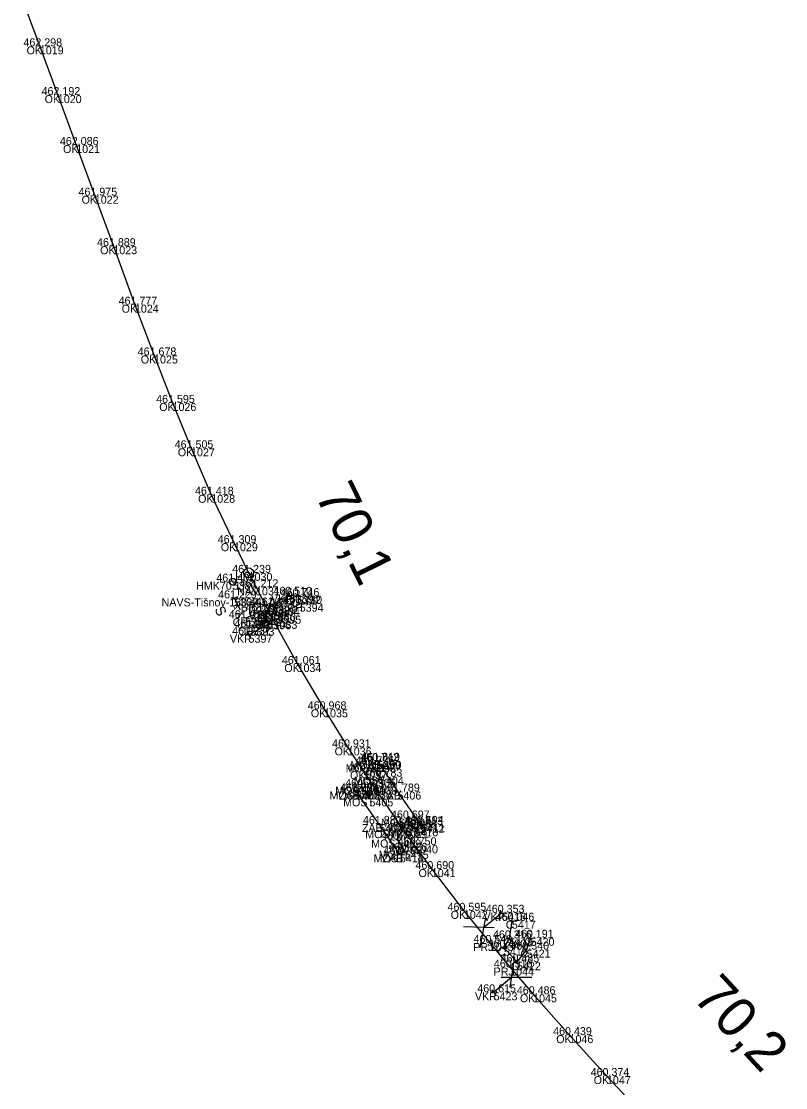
# Model space of a CAD drawing. Extents: x -621782 to -610392, y -1141853 to -1122321.
# Drawn here: x -621297.7 to -621183, y -1126701.5 to -1126541.6 of the extents above; entities that cross this region are included whole.
import ezdxf

# ---------------------------------------------------------------- set-up
doc = ezdxf.new("R2010")
doc.units = 0
for name, color, linetype in [('Vrstva 1', 7, 'Continuous'), ('Vrstva 17', 7, 'Continuous'), ('Vrstva 18', 7, 'Continuous'), ('Vrstva 4', 7, 'Continuous'), ('Vrstva 51', 7, 'Continuous'), ('Vrstva 6', 7, 'Continuous'), ('Vrstva 60', 7, 'Continuous'), ('Vrstva 61', 7, 'Continuous'), ('Vrstva 62', 7, 'Continuous'), ('Vrstva 7', 7, 'Continuous')]:
    doc.layers.add(name, color=color, linetype=linetype)

msp = doc.modelspace()

# ---------------------------------------------------------------- linework, layer by layer
at = {"layer": 'Vrstva 1'}
msp.add_lwpolyline([(-621297.67, -1126537.82), (-621294.89, -1126545.32), (-621292.19, -1126552.63), (-621289.43, -1126560.12), (-621286.64, -1126567.72), (-621283.86, -1126575.29), (-621280.62, -1126584.06), (-621277.75, -1126591.68), (-621274.98, -1126598.8), (-621272.2, -1126605.6), (-621269.16, -1126612.57), (-621265.75, -1126619.83), (-621263.56, -1126624.28), (-621262.45, -1126626.44), (-621260.94, -1126629.35), (-621259.82, -1126631.47), (-621256.22, -1126637.95), (-621252.24, -1126644.74), (-621248.68, -1126650.45), (-621246.36, -1126654.03), (-621244.83, -1126656.34), (-621240.33, -1126662.87), (-621238.72, -1126665.13), (-621236.08, -1126668.7), (-621231.26, -1126674.96), (-621227.37, -1126679.78), (-621224.31, -1126683.46), (-621220.87, -1126687.47), (-621215.41, -1126693.6), (-621209.79, -1126699.74), (-621206.18, -1126703.65)], dxfattribs=at)
at = {"layer": 'Vrstva 17'}
for points in [[(-621244.2, -1126652.45), (-621241.23, -1126657.07), (-621237.76, -1126662.06)], [(-621240.87, -1126666.49), (-621243.96, -1126661.94), (-621247.42, -1126657.07)]]:
    msp.add_lwpolyline(points, dxfattribs=at)
at = {"layer": 'Vrstva 18'}
for points in [[(-621247.48, -1126657.05), (-621246.62, -1126656.41), (-621245.43, -1126658.09), (-621243.85, -1126654.85), (-621245.06, -1126652.97), (-621244.35, -1126652.51)], [(-621240.87, -1126666.49), (-621240.11, -1126665.96), (-621241.24, -1126664.27), (-621239.75, -1126661.12), (-621238.67, -1126662.6), (-621237.66, -1126661.92)]]:
    msp.add_lwpolyline(points, dxfattribs=at)
at = {"layer": 'Vrstva 4'}
for p, q in [((-621261.55, -1126632.16), (-621259.94, -1126627.83)), ((-621257.4, -1126627.57), (-621260.48, -1126629.28)), ((-621257.16, -1126628.01), (-621257.65, -1126627.13)), ((-621258.97, -1126629.58), (-621263.49, -1126628.66)), ((-621259.43, -1126628.97), (-621261.03, -1126633.29)), ((-621260.94, -1126629.35), (-621259.82, -1126631.47)), ((-621263.57, -1126633.56), (-621260.5, -1126631.85)), ((-621262.01, -1126631.54), (-621257.49, -1126632.46)), ((-621263.82, -1126633.12), (-621263.33, -1126633.99)), ((-621228.82, -1126680.49), (-621227.98, -1126675.96)), ((-621225.52, -1126675.26), (-621228.26, -1126677.47)), ((-621225.21, -1126675.65), (-621225.83, -1126674.87)), ((-621226.72, -1126677.51), (-621231.33, -1126677.38)), ((-621227.37, -1126679.78), (-621224.31, -1126683.46)), ((-621223.66, -1126681.86), (-621224.36, -1126686.41)), ((-621226.8, -1126687.18), (-621224.13, -1126684.89)), ((-621225.66, -1126684.89), (-621221.06, -1126684.89)), ((-621227.12, -1126686.8), (-621226.47, -1126687.56))]:
    msp.add_line(p, q, dxfattribs=at)
at = {"layer": 'Vrstva 51'}
for points in [[(-621256.3, -1126627.77), (-621260.03, -1126629.17), (-621259.23, -1126630.7), (-621255.89, -1126628.9)], [(-621264.08, -1126631.09), (-621261.57, -1126630.03), (-621260.77, -1126631.54), (-621263.26, -1126632.48)], [(-621224.05, -1126676.44), (-621224.45, -1126679.1), (-621225.25, -1126680.47), (-621223.29, -1126682.67), (-621221.83, -1126680.78), (-621221.24, -1126679)]]:
    msp.add_lwpolyline(points, dxfattribs=at)
at = {"layer": 'Vrstva 6'}
for p, q in [((-621265.24, -1126627.87), (-621266.13, -1126628.33)), ((-621264.77, -1126629.85), (-621265.69, -1126628.1))]:
    msp.add_line(p, q, dxfattribs=at)
at = {"layer": 'Vrstva 60'}
for p, q in [((-621294.89, -1126545.32), (-621294.89, -1126545.32)), ((-621292.19, -1126552.63), (-621292.19, -1126552.63)), ((-621289.43, -1126560.12), (-621289.43, -1126560.12)), ((-621286.64, -1126567.72), (-621286.64, -1126567.72)), ((-621283.86, -1126575.29), (-621283.86, -1126575.29)), ((-621280.62, -1126584.06), (-621280.62, -1126584.06)), ((-621277.75, -1126591.68), (-621277.75, -1126591.68)), ((-621274.98, -1126598.8), (-621274.98, -1126598.8)), ((-621272.2, -1126605.6), (-621272.2, -1126605.6)), ((-621269.16, -1126612.57), (-621269.16, -1126612.57)), ((-621265.75, -1126619.83), (-621265.75, -1126619.83)), ((-621263.56, -1126624.28), (-621263.56, -1126624.28)), ((-621265.96, -1126625.6), (-621265.96, -1126625.6)), ((-621262.45, -1126626.44), (-621262.45, -1126626.44)), ((-621257.4, -1126627.57), (-621257.4, -1126627.57)), ((-621256.3, -1126627.77), (-621256.3, -1126627.77)), ((-621265.69, -1126628.1), (-621265.69, -1126628.1)), ((-621260.94, -1126629.35), (-621260.94, -1126629.35)), ((-621260.03, -1126629.17), (-621260.03, -1126629.17)), ((-621255.89, -1126628.9), (-621255.89, -1126628.9)), ((-621264.08, -1126631.09), (-621264.08, -1126631.09)), ((-621261.57, -1126630.03), (-621261.57, -1126630.03)), ((-621259.23, -1126630.7), (-621259.23, -1126630.7)), ((-621263.26, -1126632.48), (-621263.26, -1126632.48)), ((-621260.77, -1126631.54), (-621260.77, -1126631.54)), ((-621259.82, -1126631.47), (-621259.82, -1126631.47)), ((-621263.57, -1126633.56), (-621263.57, -1126633.56)), ((-621256.22, -1126637.95), (-621256.22, -1126637.95)), ((-621252.24, -1126644.74), (-621252.24, -1126644.74)), ((-621248.68, -1126650.45), (-621248.68, -1126650.45)), ((-621245.06, -1126652.97), (-621245.06, -1126652.97)), ((-621244.35, -1126652.51), (-621244.35, -1126652.51)), ((-621244.2, -1126652.45), (-621244.2, -1126652.45)), ((-621246.36, -1126654.03), (-621246.36, -1126654.03)), ((-621243.85, -1126654.85), (-621243.85, -1126654.85)), ((-621246.62, -1126656.41), (-621246.62, -1126656.41)), ((-621244.83, -1126656.34), (-621244.83, -1126656.34)), ((-621247.48, -1126657.05), (-621247.48, -1126657.05)), ((-621247.42, -1126657.07), (-621247.42, -1126657.07)), ((-621245.43, -1126658.09), (-621245.43, -1126658.09)), ((-621241.23, -1126657.07), (-621241.23, -1126657.07)), ((-621239.75, -1126661.12), (-621239.75, -1126661.12)), ((-621243.96, -1126661.94), (-621243.96, -1126661.94)), ((-621240.33, -1126662.87), (-621240.33, -1126662.87)), ((-621238.67, -1126662.6), (-621238.67, -1126662.6)), ((-621237.76, -1126662.06), (-621237.76, -1126662.06)), ((-621237.66, -1126661.92), (-621237.66, -1126661.92)), ((-621241.24, -1126664.27), (-621241.24, -1126664.27)), ((-621240.11, -1126665.96), (-621240.11, -1126665.96)), ((-621238.72, -1126665.13), (-621238.72, -1126665.13)), ((-621240.87, -1126666.49), (-621240.87, -1126666.49)), ((-621240.87, -1126666.49), (-621240.87, -1126666.49)), ((-621236.08, -1126668.7), (-621236.08, -1126668.7)), ((-621231.26, -1126674.96), (-621231.26, -1126674.96)), ((-621225.52, -1126675.26), (-621225.52, -1126675.26)), ((-621224.05, -1126676.44), (-621224.05, -1126676.44)), ((-621224.45, -1126679.1), (-621224.45, -1126679.1)), ((-621221.24, -1126679), (-621221.24, -1126679)), ((-621227.37, -1126679.78), (-621227.37, -1126679.78)), ((-621225.25, -1126680.47), (-621225.25, -1126680.47)), ((-621221.83, -1126680.78), (-621221.83, -1126680.78)), ((-621224.31, -1126683.46), (-621224.31, -1126683.46)), ((-621223.29, -1126682.67), (-621223.29, -1126682.67)), ((-621226.8, -1126687.18), (-621226.8, -1126687.18)), ((-621220.87, -1126687.47), (-621220.87, -1126687.47)), ((-621215.41, -1126693.6), (-621215.41, -1126693.6)), ((-621209.79, -1126699.74), (-621209.79, -1126699.74))]:
    msp.add_line(p, q, dxfattribs=at)
at = {"layer": 'Vrstva 7'}
msp.add_line((-621265.98, -1126625.56), (-621265.94, -1126625.65), dxfattribs=at)
for centre, radius in [((-621263.56, -1126624.28), 0.75), ((-621265.96, -1126625.6), 0.5)]:
    msp.add_circle(centre, radius, dxfattribs=at)

# ---------------------------------------------------------------- texts
at = {"layer": 'Vrstva 6'}
for s, height, p in [('S', 1.5, (-621268.72, -1126629.74)), ('  A A ', 1, (-621266.57, -1126628.56))]:
    msp.add_text(s, height=height, rotation=297.4168, dxfattribs=at).set_placement(p)
at = {"layer": 'Vrstva 60'}
for s, p in [('1019', (-621294.89, -1126546.52)), ('1020', (-621292.19, -1126553.83)), ('1021', (-621289.43, -1126561.32)), ('1022', (-621286.64, -1126568.92)), ('1023', (-621283.86, -1126576.49)), ('1024', (-621280.62, -1126585.26)), ('1025', (-621277.75, -1126592.88)), ('1026', (-621274.98, -1126600)), ('1027', (-621272.2, -1126606.8)), ('1028', (-621269.16, -1126613.77)), ('1029', (-621265.75, -1126621.03)), ('1030', (-621263.56, -1126625.48)), ('5386', (-621265.96, -1126626.8)), ('1031', (-621262.45, -1126627.64)), ('5389', (-621257.4, -1126628.77)), ('5392', (-621256.3, -1126628.97)), ('5387', (-621265.69, -1126629.3)), ('1032', (-621260.94, -1126630.55)), ('5390', (-621260.03, -1126630.37)), ('5394', (-621255.89, -1126630.1)), ('5388', (-621264.08, -1126632.29)), ('5391', (-621261.57, -1126631.23)), ('5395', (-621259.23, -1126631.9)), ('5393', (-621263.26, -1126633.68)), ('5396', (-621260.77, -1126632.74)), ('1033', (-621259.82, -1126632.67)), ('5397', (-621263.57, -1126634.76)), ('1034', (-621256.22, -1126639.15)), ('1035', (-621252.24, -1126645.94)), ('1036', (-621248.68, -1126651.65)), ('5398', (-621245.06, -1126654.17)), ('5399', (-621244.35, -1126653.71)), ('5400', (-621244.2, -1126653.65)), ('1037', (-621246.36, -1126655.23)), ('5404', (-621243.85, -1126656.05)), ('5401', (-621246.62, -1126657.61)), ('1038', (-621244.83, -1126657.54)), ('5402', (-621247.48, -1126658.25)), ('5403', (-621247.42, -1126658.27)), ('5405', (-621245.43, -1126659.29)), ('5406', (-621241.23, -1126658.27)), ('5408', (-621239.75, -1126662.32)), ('5407', (-621243.96, -1126663.14)), ('1039', (-621240.33, -1126664.07)), ('5410', (-621238.67, -1126663.8)), ('5412', (-621237.76, -1126663.26)), ('5411', (-621237.66, -1126663.11)), ('5409', (-621241.24, -1126665.47)), ('5415', (-621240.11, -1126667.16)), ('1040', (-621238.72, -1126666.33)), ('5413', (-621240.87, -1126667.69)), ('5414', (-621240.87, -1126667.69)), ('1041', (-621236.08, -1126669.9)), ('1042', (-621231.26, -1126676.16)), ('5416', (-621225.52, -1126676.46)), ('5417', (-621224.05, -1126677.64)), ('5418', (-621224.45, -1126680.3)), ('5420', (-621221.24, -1126680.2)), ('1043', (-621227.37, -1126680.98)), ('5419', (-621225.25, -1126681.67)), ('5421', (-621221.83, -1126681.98)), ('1044', (-621224.31, -1126684.66)), ('5422', (-621223.29, -1126683.87)), ('5423', (-621226.8, -1126688.38)), ('1045', (-621220.87, -1126688.67)), ('1046', (-621215.41, -1126694.8)), ('1047', (-621209.79, -1126700.94))]:
    msp.add_text(s, height=1.2, dxfattribs=at).set_placement(p)
at = {"layer": 'Vrstva 61'}
for s, p in [('462.298', (-621297.35, -1126545.32)), ('462.192', (-621294.63, -1126552.63)), ('462.086', (-621291.88, -1126560.12)), ('461.975', (-621289.09, -1126567.72)), ('461.889', (-621286.31, -1126575.29)), ('461.777', (-621283.07, -1126584.06)), ('461.678', (-621280.21, -1126591.68)), ('461.595', (-621277.44, -1126598.8)), ('461.505', (-621274.66, -1126605.6)), ('461.418', (-621271.61, -1126612.57)), ('461.309', (-621268.2, -1126619.83)), ('461.239', (-621266.02, -1126624.28)), ('461.402', (-621268.41, -1126625.6)), ('461.212', (-621264.9, -1126626.44)), ('460.510', (-621259.85, -1126627.57)), ('461.229', (-621268.14, -1126628.1)), ('461.142', (-621262.48, -1126629.17)), ('460.746', (-621258.75, -1126627.77)), ('460.730', (-621258.34, -1126628.9)), ('461.202', (-621264.02, -1126630.03)), ('461.167', (-621263.39, -1126629.35)), ('461.104', (-621261.68, -1126630.7)), ('461.014', (-621266.54, -1126631.09)), ('461.185', (-621263.23, -1126631.54)), ('461.140', (-621262.27, -1126631.47)), ('460.937', (-621266.03, -1126633.56)), ('461.029', (-621265.71, -1126632.48)), ('461.061', (-621258.57, -1126637.95)), ('460.968', (-621254.69, -1126644.74)), ('460.931', (-621251.04, -1126650.45)), ('460.776', (-621247.51, -1126652.97)), ('460.742', (-621246.8, -1126652.51)), ('461.819', (-621246.66, -1126652.45)), ('460.911', (-621248.72, -1126654.03)), ('460.905', (-621247.28, -1126656.34)), ('460.783', (-621246.3, -1126654.85)), ('461.898', (-621249.87, -1126657.07)), ('460.771', (-621249.84, -1126657.05)), ('460.795', (-621249.08, -1126656.41)), ('461.789', (-621243.68, -1126657.07)), ('460.838', (-621247.89, -1126658.09)), ('460.697', (-621242.2, -1126661.12)), ('461.880', (-621246.41, -1126661.94)), ('460.658', (-621241.13, -1126662.6)), ('461.713', (-621240.21, -1126662.06)), ('460.594', (-621240.11, -1126661.92)), ('460.754', (-621243.69, -1126664.27)), ('460.805', (-621242.78, -1126662.87)), ('460.726', (-621242.56, -1126665.96)), ('460.750', (-621241.17, -1126665.13)), ('461.792', (-621243.32, -1126666.49)), ('460.708', (-621243.32, -1126666.49)), ('460.690', (-621238.53, -1126668.7)), ('460.595', (-621233.71, -1126674.96)), ('460.353', (-621227.97, -1126675.26)), ('460.046', (-621226.5, -1126676.44)), ('460.549', (-621229.82, -1126679.78)), ('460.316', (-621226.9, -1126679.1)), ('460.191', (-621223.6, -1126679)), ('460.480', (-621227.7, -1126680.47)), ('460.340', (-621224.28, -1126680.78)), ('460.516', (-621226.76, -1126683.46)), ('460.485', (-621225.75, -1126682.67)), ('460.615', (-621229.25, -1126687.18)), ('460.486', (-621223.32, -1126687.47)), ('460.439', (-621217.87, -1126693.6)), ('460.374', (-621212.24, -1126699.74))]:
    msp.add_text(s, height=1.2, dxfattribs=at).set_placement(p)
at = {"layer": 'Vrstva 62'}
for s, p in [('OK', (-621296.88, -1126546.52)), ('OK', (-621294.17, -1126553.83)), ('OK', (-621291.41, -1126561.32)), ('OK', (-621288.62, -1126568.92)), ('OK', (-621285.84, -1126576.49)), ('OK', (-621282.61, -1126585.26)), ('OK', (-621279.74, -1126592.88)), ('OK', (-621276.97, -1126600)), ('OK', (-621274.18, -1126606.8)), ('OK', (-621271.14, -1126613.77)), ('OK', (-621267.73, -1126621.03)), ('HM', (-621265.6, -1126625.48)), ('HMK70.1', (-621271.44, -1126626.8)), ('NAV', (-621265.27, -1126627.64)), ('VKR', (-621260.21, -1126628.77)), ('CH', (-621258.17, -1126628.97)), ('NAVS-Tišnov-130', (-621276.62, -1126629.3)), ('PRCH', (-621264.72, -1126630.55)), ('CH', (-621261.9, -1126630.37)), ('CH', (-621257.76, -1126630.1)), ('CH', (-621265.95, -1126632.29)), ('CH', (-621263.44, -1126631.23)), ('CH', (-621261.1, -1126631.9)), ('CH', (-621265.13, -1126633.68)), ('PRCH', (-621263.6, -1126632.67)), ('CH', (-621262.64, -1126632.74)), ('VKR', (-621266.38, -1126634.76)), ('OK', (-621258.2, -1126639.15)), ('OK', (-621254.22, -1126645.94)), ('OK', (-621250.66, -1126651.65)), ('MOST', (-621249, -1126654.17)), ('MOST', (-621248.3, -1126653.71)), ('ZAB', (-621246.8, -1126653.65)), ('OK', (-621248.35, -1126655.23)), ('MOST', (-621247.79, -1126656.05)), ('MOSTBS', (-621250.56, -1126657.54)), ('MOST', (-621250.56, -1126657.61)), ('MOST', (-621251.43, -1126658.25)), ('ZAB', (-621250.02, -1126658.27)), ('MOST', (-621249.38, -1126659.29)), ('ZAB', (-621243.83, -1126658.27)), ('MOST', (-621243.69, -1126662.32)), ('ZAB', (-621246.56, -1126663.14)), ('MOSTBS', (-621246.06, -1126664.07)), ('MOST', (-621242.62, -1126663.8)), ('MOST', (-621241.6, -1126663.11)), ('ZAB', (-621240.36, -1126663.26)), ('MOST', (-621245.18, -1126665.47)), ('MOST', (-621244.05, -1126667.16)), ('OK', (-621240.7, -1126666.33)), ('MOST', (-621244.81, -1126667.69)), ('ZAB', (-621243.48, -1126667.69)), ('OK', (-621238.07, -1126669.9)), ('OK', (-621233.24, -1126676.16)), ('VKR', (-621228.33, -1126676.46)), ('C', (-621224.98, -1126677.64)), ('C', (-621225.38, -1126680.3)), ('C', (-621222.18, -1126680.2)), ('PRJ', (-621229.86, -1126680.98)), ('C', (-621226.19, -1126681.67)), ('C', (-621222.76, -1126681.98)), ('PRJ', (-621226.8, -1126684.66)), ('C', (-621224.22, -1126683.87)), ('VKR', (-621229.6, -1126688.38)), ('OK', (-621222.85, -1126688.67)), ('OK', (-621217.4, -1126694.8)), ('OK', (-621211.78, -1126700.94))]:
    msp.add_text(s, height=1.2, dxfattribs=at).set_placement(p)
at = {"layer": 'Vrstva 7'}
for s, rotation, p in [('70,1', 296.1978, (-621253.67, -1126612.56)), ('70,2', 312.8138, (-621197.11, -1126688.04))]:
    msp.add_text(s, height=6, rotation=rotation, dxfattribs=at).set_placement(p)

doc.saveas('drawing.dxf')
